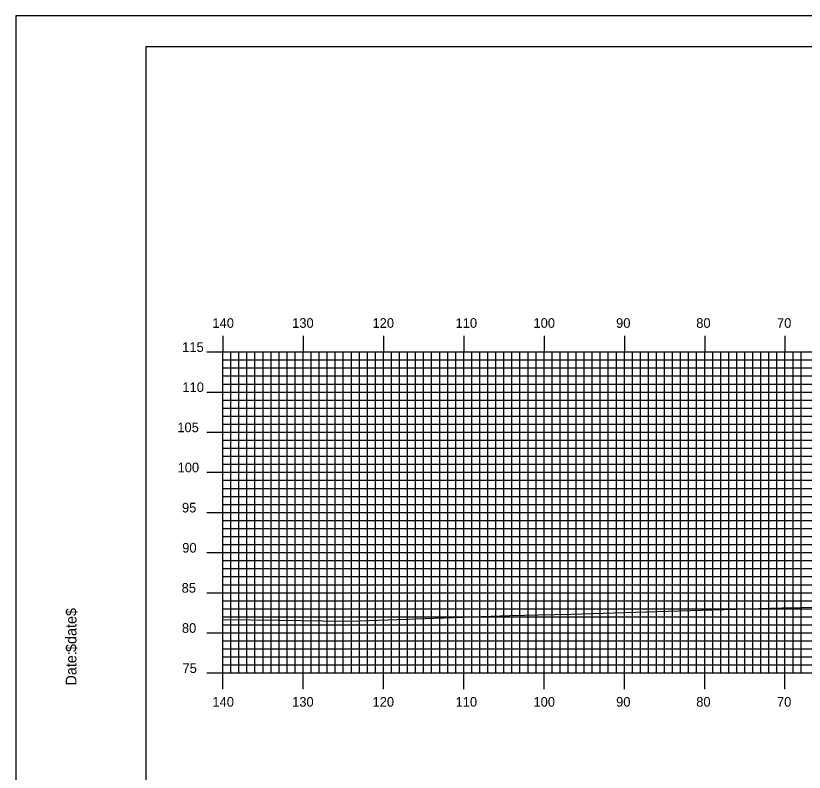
# Model space of a CAD drawing. Extents: x 1759823 to 1760167, y 442591 to 442811.
# Drawn here: x 1759823.4 to 1759921.6, y 442716.3 to 442810.5 of the extents above; entities that cross this region are included whole.
import ezdxf

# ---------------------------------------------------------------- set-up
doc = ezdxf.new("R2010")
doc.units = 0
for name, color, linetype in [('BORDER', 7, 'Continuous'), ('H_V ANNOTATION', 7, 'Continuous'), ('MAJOR', 7, 'Continuous'), ('MINOR', 7, 'Continuous'), ('PLOT BOUNDARY', 7, 'Continuous'), ('S_Roadway_Centerline', 7, 'Continuous')]:
    doc.layers.add(name, color=color, linetype=linetype)

msp = doc.modelspace()

# ---------------------------------------------------------------- linework, layer by layer
at = {"layer": 'BORDER'}
msp.add_lwpolyline([(1759839.588, 442596.665), (1760159.588, 442596.665), (1760159.588, 442806.665), (1759839.588, 442806.665)], close=True, dxfattribs=at)
at = {"layer": 'MAJOR'}
for p, q in [((1759849.188, 442770.669), (1759849.188, 442768.665)), ((1759859.188, 442770.669), (1759859.188, 442768.665)), ((1759869.188, 442770.669), (1759869.188, 442768.665)), ((1759879.188, 442770.669), (1759879.188, 442768.665)), ((1759889.188, 442770.669), (1759889.188, 442768.665)), ((1759899.188, 442770.669), (1759899.188, 442768.665)), ((1759909.188, 442770.669), (1759909.188, 442768.665)), ((1759919.188, 442770.669), (1759919.188, 442768.665)), ((1759847.184, 442768.665), (1759849.188, 442768.665)), ((1759849.188, 442768.665), (1760129.188, 442768.665)), ((1759849.188, 442728.665), (1759849.188, 442768.665)), ((1759849.188, 442728.665), (1759849.188, 442768.665)), ((1759849.188, 442768.665), (1760129.188, 442768.665)), ((1759859.188, 442728.665), (1759859.188, 442768.665)), ((1759869.188, 442728.665), (1759869.188, 442768.665)), ((1759879.188, 442728.665), (1759879.188, 442768.665)), ((1759889.188, 442728.665), (1759889.188, 442768.665)), ((1759899.188, 442728.665), (1759899.188, 442768.665)), ((1759909.188, 442728.665), (1759909.188, 442768.665)), ((1759919.188, 442728.665), (1759919.188, 442768.665)), ((1759847.184, 442763.665), (1759849.188, 442763.665)), ((1759849.188, 442763.665), (1760129.188, 442763.665)), ((1759847.184, 442758.665), (1759849.188, 442758.665)), ((1759849.188, 442758.665), (1760129.188, 442758.665)), ((1759847.184, 442753.665), (1759849.188, 442753.665)), ((1759849.188, 442753.665), (1760129.188, 442753.665)), ((1759847.184, 442748.665), (1759849.188, 442748.665)), ((1759849.188, 442748.665), (1760129.188, 442748.665)), ((1759847.184, 442743.665), (1759849.188, 442743.665)), ((1759849.188, 442743.665), (1760129.188, 442743.665)), ((1759847.184, 442738.665), (1759849.188, 442738.665)), ((1759849.188, 442738.665), (1760129.188, 442738.665)), ((1759847.184, 442733.665), (1759849.188, 442733.665)), ((1759849.188, 442733.665), (1760129.188, 442733.665)), ((1759847.184, 442728.665), (1759849.188, 442728.665)), ((1759849.188, 442728.665), (1760129.188, 442728.665)), ((1759849.188, 442728.665), (1760129.188, 442728.665)), ((1759849.188, 442726.661), (1759849.188, 442728.665)), ((1759859.188, 442726.661), (1759859.188, 442728.665)), ((1759869.188, 442726.661), (1759869.188, 442728.665)), ((1759879.188, 442726.661), (1759879.188, 442728.665)), ((1759889.188, 442726.661), (1759889.188, 442728.665)), ((1759899.188, 442726.661), (1759899.188, 442728.665)), ((1759909.188, 442726.661), (1759909.188, 442728.665)), ((1759919.188, 442726.661), (1759919.188, 442728.665))]:
    msp.add_line(p, q, dxfattribs=at)
at = {"layer": 'MINOR'}
for p, q in [((1759850.188, 442728.665), (1759850.188, 442768.665)), ((1759851.188, 442728.665), (1759851.188, 442768.665)), ((1759852.188, 442728.665), (1759852.188, 442768.665)), ((1759853.188, 442728.665), (1759853.188, 442768.665)), ((1759854.188, 442728.665), (1759854.188, 442768.665)), ((1759855.188, 442728.665), (1759855.188, 442768.665)), ((1759856.188, 442728.665), (1759856.188, 442768.665)), ((1759857.188, 442728.665), (1759857.188, 442768.665)), ((1759858.188, 442728.665), (1759858.188, 442768.665)), ((1759860.188, 442728.665), (1759860.188, 442768.665)), ((1759861.188, 442728.665), (1759861.188, 442768.665)), ((1759862.188, 442728.665), (1759862.188, 442768.665)), ((1759863.188, 442728.665), (1759863.188, 442768.665)), ((1759864.188, 442728.665), (1759864.188, 442768.665)), ((1759865.188, 442728.665), (1759865.188, 442768.665)), ((1759866.188, 442728.665), (1759866.188, 442768.665)), ((1759867.188, 442728.665), (1759867.188, 442768.665)), ((1759868.188, 442728.665), (1759868.188, 442768.665)), ((1759870.188, 442728.665), (1759870.188, 442768.665)), ((1759871.188, 442728.665), (1759871.188, 442768.665)), ((1759872.188, 442728.665), (1759872.188, 442768.665)), ((1759873.188, 442728.665), (1759873.188, 442768.665)), ((1759874.188, 442728.665), (1759874.188, 442768.665)), ((1759875.188, 442728.665), (1759875.188, 442768.665)), ((1759876.188, 442728.665), (1759876.188, 442768.665)), ((1759877.188, 442728.665), (1759877.188, 442768.665)), ((1759878.188, 442728.665), (1759878.188, 442768.665)), ((1759880.188, 442728.665), (1759880.188, 442768.665)), ((1759881.188, 442728.665), (1759881.188, 442768.665)), ((1759882.188, 442728.665), (1759882.188, 442768.665)), ((1759883.188, 442728.665), (1759883.188, 442768.665)), ((1759884.188, 442728.665), (1759884.188, 442768.665)), ((1759885.188, 442728.665), (1759885.188, 442768.665)), ((1759886.188, 442728.665), (1759886.188, 442768.665)), ((1759887.188, 442728.665), (1759887.188, 442768.665)), ((1759888.188, 442728.665), (1759888.188, 442768.665)), ((1759890.188, 442728.665), (1759890.188, 442768.665)), ((1759891.188, 442728.665), (1759891.188, 442768.665)), ((1759892.188, 442728.665), (1759892.188, 442768.665)), ((1759893.188, 442728.665), (1759893.188, 442768.665)), ((1759894.188, 442728.665), (1759894.188, 442768.665)), ((1759895.188, 442728.665), (1759895.188, 442768.665)), ((1759896.188, 442728.665), (1759896.188, 442768.665)), ((1759897.188, 442728.665), (1759897.188, 442768.665)), ((1759898.188, 442728.665), (1759898.188, 442768.665)), ((1759900.188, 442728.665), (1759900.188, 442768.665)), ((1759901.188, 442728.665), (1759901.188, 442768.665)), ((1759902.188, 442728.665), (1759902.188, 442768.665)), ((1759903.188, 442728.665), (1759903.188, 442768.665)), ((1759904.188, 442728.665), (1759904.188, 442768.665)), ((1759905.188, 442728.665), (1759905.188, 442768.665)), ((1759906.188, 442728.665), (1759906.188, 442768.665)), ((1759907.188, 442728.665), (1759907.188, 442768.665)), ((1759908.188, 442728.665), (1759908.188, 442768.665)), ((1759910.188, 442728.665), (1759910.188, 442768.665)), ((1759911.188, 442728.665), (1759911.188, 442768.665)), ((1759912.188, 442728.665), (1759912.188, 442768.665)), ((1759913.188, 442728.665), (1759913.188, 442768.665)), ((1759914.188, 442728.665), (1759914.188, 442768.665)), ((1759915.188, 442728.665), (1759915.188, 442768.665)), ((1759916.188, 442728.665), (1759916.188, 442768.665)), ((1759917.188, 442728.665), (1759917.188, 442768.665)), ((1759918.188, 442728.665), (1759918.188, 442768.665)), ((1759920.188, 442728.665), (1759920.188, 442768.665)), ((1759921.188, 442728.665), (1759921.188, 442768.665)), ((1759849.188, 442767.665), (1760129.188, 442767.665)), ((1759849.188, 442767.665), (1759851.192, 442767.665)), ((1759849.188, 442766.665), (1760129.188, 442766.665)), ((1759849.188, 442766.665), (1759851.192, 442766.665)), ((1759849.188, 442765.665), (1760129.188, 442765.665)), ((1759849.188, 442765.665), (1759851.192, 442765.665)), ((1759849.188, 442764.665), (1760129.188, 442764.665)), ((1759849.188, 442764.665), (1759851.192, 442764.665)), ((1759849.188, 442762.665), (1760129.188, 442762.665)), ((1759849.188, 442762.665), (1759851.192, 442762.665)), ((1759849.188, 442761.665), (1760129.188, 442761.665)), ((1759849.188, 442761.665), (1759851.192, 442761.665)), ((1759849.188, 442760.665), (1760129.188, 442760.665)), ((1759849.188, 442760.665), (1759851.192, 442760.665)), ((1759849.188, 442759.665), (1760129.188, 442759.665)), ((1759849.188, 442759.665), (1759851.192, 442759.665)), ((1759849.188, 442757.665), (1760129.188, 442757.665)), ((1759849.188, 442757.665), (1759851.192, 442757.665)), ((1759849.188, 442756.665), (1760129.188, 442756.665)), ((1759849.188, 442756.665), (1759851.192, 442756.665)), ((1759849.188, 442755.665), (1760129.188, 442755.665)), ((1759849.188, 442755.665), (1759851.192, 442755.665)), ((1759849.188, 442754.665), (1760129.188, 442754.665)), ((1759849.188, 442754.665), (1759851.192, 442754.665)), ((1759849.188, 442752.665), (1760129.188, 442752.665)), ((1759849.188, 442752.665), (1759851.192, 442752.665)), ((1759849.188, 442751.665), (1760129.188, 442751.665)), ((1759849.188, 442751.665), (1759851.192, 442751.665)), ((1759849.188, 442750.665), (1760129.188, 442750.665)), ((1759849.188, 442750.665), (1759851.192, 442750.665)), ((1759849.188, 442749.665), (1760129.188, 442749.665)), ((1759849.188, 442749.665), (1759851.192, 442749.665)), ((1759849.188, 442747.665), (1760129.188, 442747.665)), ((1759849.188, 442747.665), (1759851.192, 442747.665)), ((1759849.188, 442746.665), (1760129.188, 442746.665)), ((1759849.188, 442746.665), (1759851.192, 442746.665)), ((1759849.188, 442745.665), (1760129.188, 442745.665)), ((1759849.188, 442745.665), (1759851.192, 442745.665)), ((1759849.188, 442744.665), (1760129.188, 442744.665)), ((1759849.188, 442744.665), (1759851.192, 442744.665)), ((1759849.188, 442742.665), (1760129.188, 442742.665)), ((1759849.188, 442742.665), (1759851.192, 442742.665)), ((1759849.188, 442741.665), (1760129.188, 442741.665)), ((1759849.188, 442741.665), (1759851.192, 442741.665)), ((1759849.188, 442740.665), (1760129.188, 442740.665)), ((1759849.188, 442740.665), (1759851.192, 442740.665)), ((1759849.188, 442739.665), (1760129.188, 442739.665)), ((1759849.188, 442739.665), (1759851.192, 442739.665)), ((1759849.188, 442737.665), (1760129.188, 442737.665)), ((1759849.188, 442737.665), (1759851.192, 442737.665)), ((1759849.188, 442736.665), (1760129.188, 442736.665)), ((1759849.188, 442736.665), (1759851.192, 442736.665)), ((1759849.188, 442735.665), (1760129.188, 442735.665)), ((1759849.188, 442735.665), (1759851.192, 442735.665)), ((1759849.188, 442734.665), (1760129.188, 442734.665)), ((1759849.188, 442734.665), (1759851.192, 442734.665)), ((1759849.188, 442732.665), (1760129.188, 442732.665)), ((1759849.188, 442732.665), (1759851.192, 442732.665)), ((1759849.188, 442731.665), (1760129.188, 442731.665)), ((1759849.188, 442731.665), (1759851.192, 442731.665)), ((1759849.188, 442730.665), (1760129.188, 442730.665)), ((1759849.188, 442730.665), (1759851.192, 442730.665)), ((1759849.188, 442729.665), (1760129.188, 442729.665)), ((1759849.188, 442729.665), (1759851.192, 442729.665))]:
    msp.add_line(p, q, dxfattribs=at)
at = {"layer": 'PLOT BOUNDARY'}
msp.add_lwpolyline([(1759823.401, 442590.547), (1760163.401, 442590.547), (1760163.401, 442810.547), (1759823.401, 442810.547)], close=True, dxfattribs=at)
at = {"layer": 'S_Roadway_Centerline'}
msp.add_lwpolyline([(1759849.188, 442735.323), (1759856.264, 442735.23), (1759864.275, 442735.112), (1759866.185, 442735.163), (1759884.927, 442735.839), (1759888.478, 442735.899), (1759892.58, 442735.995), (1759905.99, 442736.418), (1759911.621, 442736.589), (1759918.825, 442736.786), (1759923.718, 442736.877), (1759927.75, 442736.96), (1759944.69, 442737.056), (1759948.486, 442737.034), (1759969.962, 442737.101), (1759969.967, 442737.101), (1759969.972, 442737.102), (1759981.654, 442737.463), (1759990.981, 442737.401), (1759996.733, 442737.601), (1760012.195, 442738.192), (1760022.278, 442738.699), (1760033.54, 442739.126)], dxfattribs=at)

# ---------------------------------------------------------------- texts
at = {"layer": 'BORDER'}
for s, p in [('$date$', (1759830.957, 442731.275)), ('$date$', (1759830.957, 442731.275)), ('Date:', (1759830.957, 442727.099)), ('Date:', (1759830.957, 442727.099))]:
    msp.add_text(s, height=1.3392, rotation=90, dxfattribs=at).set_placement(p)
at = {"layer": 'H_V ANNOTATION'}
for s, p in [('140', (1759847.893, 442771.665)), ('130', (1759857.818, 442771.665)), ('120', (1759867.828, 442771.665)), ('110', (1759878.171, 442771.665)), ('100', (1759887.871, 442771.665)), ('90', (1759898.16, 442771.665)), ('80', (1759908.138, 442771.665)), ('70', (1759918.192, 442771.665)), ('115', (1759844.122, 442768.665)), ('110', (1759844.154, 442763.665)), ('105', (1759843.522, 442758.665)), ('100', (1759843.554, 442753.665)), ('95', (1759844.1, 442748.665)), ('90', (1759844.132, 442743.665)), ('85', (1759844.057, 442738.665)), ('80', (1759844.089, 442733.665)), ('75', (1759844.164, 442728.665)), ('140', (1759847.893, 442724.465)), ('130', (1759857.818, 442724.465)), ('120', (1759867.828, 442724.465)), ('110', (1759878.171, 442724.465)), ('100', (1759887.871, 442724.465)), ('90', (1759898.16, 442724.465)), ('80', (1759908.138, 442724.465)), ('70', (1759918.192, 442724.465))]:
    msp.add_text(s, height=1.2, dxfattribs=at).set_placement(p)
at = {"layer": 'MAJOR'}
msp.add_text('-', height=0.012, dxfattribs=at).set_placement((1759849.179, 442728.665))

doc.saveas('drawing.dxf')
